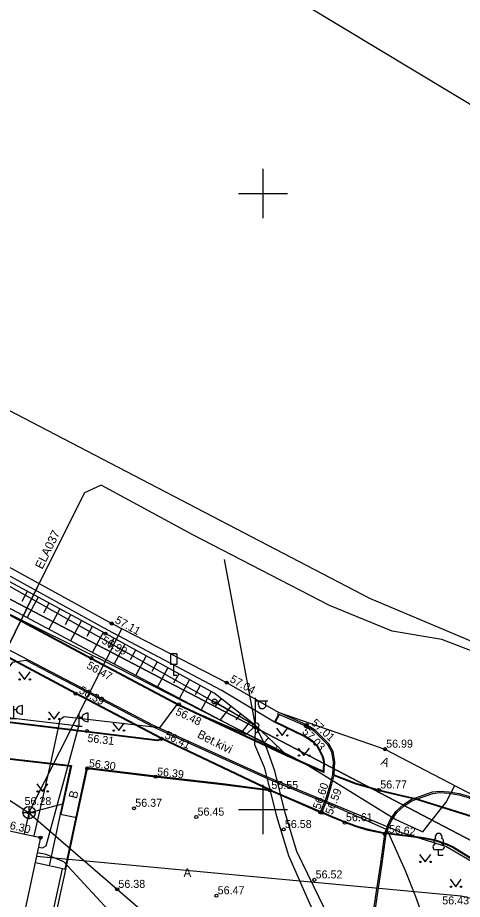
# Model space of a CAD drawing. Extents: x 542320 to 543602, y 6558748 to 6559969.
# Drawn here: x 543080.1 to 543116.2, y 6558892.7 to 6558964.3 of the extents above; entities that cross this region are included whole.
import ezdxf

# ---------------------------------------------------------------- set-up
doc = ezdxf.new("R2010")
doc.units = 0
for name, color, linetype in [('HALJASTUS', 7, 'Continuous'), ('HOONE', 7, 'Continuous'), ('HOONEDET', 7, 'Continuous'), ('KKAEV', 7, 'Continuous'), ('KORGUS-EH2000', 7, 'Continuous'), ('KTRASS', 7, 'Continuous'), ('LIIKLUS', 7, 'Continuous'), ('mootpiir', 7, 'Continuous'), ('MPKAABEL', 7, 'Continuous'), ('MPOHULIIN', 7, 'Continuous'), ('PIIR', 7, 'Continuous'), ('POST', 7, 'Continuous'), ('PUU', 7, 'Continuous'), ('RELJEEF', 7, 'Continuous'), ('SITRASS', 7, 'Continuous'), ('TEE', 7, 'Continuous'), ('VORK', 7, 'Continuous')]:
    doc.layers.add(name, color=color, linetype=linetype)

# ---------------------------------------------------------------- blocks, each defined once
blk = doc.blocks.new('VKORIS')
for p, q in [((0, 4), (0, -4)), ((-4, 0), (4, 0))]:
    blk.add_line(p, q)
blk = doc.blocks.new('LEHTP1')
for p, q in [((0.48, 0.95), (-0.48, 0.95)), ((0, 0), (0, 0.95)), ((0.76, 0), (0, 0))]:
    blk.add_line(p, q)
for centre, radius, start, end in [((0, 3.04), 0.554, 332.5799, 207.4201), ((-0.47, 1.42), 0.475, 90.0016, 269.3953), ((-0.34, 2.35), 0.465, 109.0217, 253.1415), ((0.34, 2.35), 0.465, 286.8508, 70.9859), ((0.47, 1.42), 0.475, 270.6047, 89.9984)]:
    blk.add_arc(centre, radius, start, end)
blk = doc.blocks.new('KAABVA')
for p, q in [((0, 2), (0, 0)), ((1.5, 0.69), (1.5, 2.09))]:
    blk.add_line(p, q)
for points in [[(-0.5, 0), (0.5, 0)], [(0.5, 1.39), (0, 1.39)]]:
    blk.add_lwpolyline(points)
blk.add_ellipse((1.5, 1.39), major_axis=(1, 0), ratio=0.7, start_param=1.570796, end_param=4.712389)
blk = doc.blocks.new('KAKAEV')
for p, q in [((-1, 0), (1, 0)), ((0, -1), (0, 1))]:
    blk.add_line(p, q)
blk.add_circle((0, 0), 1)
blk = doc.blocks.new('PUPOST')
blk.add_circle((0, 0), 0.5)
blk = doc.blocks.new('VAPOST')
for p, q in [((0, 0.5), (0, 4.5)), ((0, 4), (2, 4)), ((0.45, 3.36), (0.45, 4)), ((1.68, 3.36), (1.68, 4))]:
    blk.add_line(p, q)
blk.add_arc((1.07, 3.36), 0.613, 180, 0)
blk = doc.blocks.new('TUPOST')
blk.add_circle((0, 0), 0.4)
blk = doc.blocks.new('LIIKLM')
for points in [[(-0.5, 3.5), (-0.5, 1.8)], [(0.5, 3.5), (-0.5, 3.5)], [(0.5, 3.5), (0.5, 1.8)], [(0.5, 1.8), (-0.5, 1.8)], [(0, 1.8), (0, 0)], [(0.5, 0), (0, 0)]]:
    blk.add_lwpolyline(points)
blk = doc.blocks.new('MURU')
for p, q in [((-0.93, 1.21), (0, 0)), ((0, 0), (0.89, 1.21))]:
    blk.add_line(p, q)
for centre in [(-0.8, 0), (0.86, 0)]:
    blk.add_circle(centre, 0.11)
blk = doc.blocks.new('RING02')
blk.add_circle((0, 0), 0.25)

msp = doc.modelspace()

# ---------------------------------------------------------------- linework, layer by layer
at = {"layer": 'HOONE'}
msp.add_lwpolyline([(543034.683, 6558908.573), (543039.145, 6558923.204), (543048.898, 6558920.298), (543046.148, 6558911.034), (543052.456, 6558904.09), (543051.993, 6558903.334), (543059.743, 6558898.897), (543060.252, 6558899.636), (543066.159, 6558898.365), (543069.065, 6558900.487), (543081.93, 6558897.713), (543079.788, 6558887.775), (543071.384, 6558889.615), (543068.481, 6558887.445), (543058.412, 6558889.575), (543048.599, 6558888.632), (543044.558, 6558897.817)], close=True, dxfattribs=at)
at = {"layer": 'HOONEDET'}
for points in [[(543082.952, 6558890.426), (543083.981, 6558895.123), (543081.515, 6558895.656)], [(543082.694, 6558890.46), (543083.714, 6558895.181)]]:
    msp.add_lwpolyline(points, dxfattribs=at)
at = {"layer": 'KTRASS'}
for points in [[(543051.198, 6558905.487), (543058.296, 6558914.646), (543080.977, 6558899.722)], [(543080.977, 6558899.722), (543088.535, 6558914.669)], [(543080.977, 6558899.722), (543083.828, 6558900.481)], [(543080.977, 6558899.722), (543080.609, 6558898.013)], [(543080.977, 6558899.722), (543096.945, 6558885.936), (543103.523, 6558880.342)]]:
    msp.add_lwpolyline(points, dxfattribs=at)
at = {"layer": 'mootpiir'}
msp.add_lwpolyline([(543041.705, 6558842.986), (543026.57, 6558857.521), (543021.178, 6558871.989), (543014.73, 6558888.797), (543010.556, 6558896.706), (543004.564, 6558907.11), (542998.316, 6558921.614), (543000.462, 6558938.213), (543007.664, 6558949.977), (543004.131, 6558955.194), (543005.558, 6558957.946), (543018.426, 6558954.012), (543033.202, 6558945.57), (543039.476, 6558941.983), (543051.303, 6558935.01), (543063.018, 6558928.648), (543075.179, 6558921.966), (543087.717, 6558915.09), (543097.044, 6558910.296), (543101.236, 6558907.88), (543109.903, 6558904.892), (543122.322, 6558898.427)], dxfattribs=at)
at = {"layer": 'MPKAABEL'}
for points in [[(543081.761, 6558896.926), (543082.099, 6558896.873), (543082.395, 6558897.034), (543085.057, 6558906.769), (543079.727, 6558907.382), (543074.242, 6558908.071), (543068.825, 6558908.727), (543063.367, 6558909.397), (543058.921, 6558912.202), (543055.778, 6558916.692), (543052.723, 6558921.189), (543049.567, 6558925.65)], [(543099.398, 6558906.809), (543098.64, 6558906.09), (543093.01, 6558908.51), (543091.59, 6558906.63), (543083.86, 6558907.52), (543083.5, 6558907.27), (543082.75, 6558903.75), (543081.4, 6558897.86)], [(543099.403, 6558906.806), (543099.315, 6558905.267), (543100.092, 6558903.434), (543101.085, 6558899.465), (543102.078, 6558896.251), (543103.632, 6558892.692), (543104.216, 6558891.45), (543105.878, 6558886.662), (543106.439, 6558882.477), (543107.325, 6558876.083)], [(543107.994, 6558876.298), (543106.677, 6558887.105), (543105.425, 6558891.061), (543102.749, 6558896.583), (543101.807, 6558899.724), (543100.957, 6558903.142), (543100.302, 6558904.938), (543099.403, 6558906.806)], [(543091.766, 6558887.156), (543083.836, 6558895.736), (543082.377, 6558896.34), (543081.695, 6558896.464)]]:
    msp.add_lwpolyline(points, dxfattribs=at)
at = {"layer": 'MPOHULIIN'}
for points in [[(543099.403, 6558906.806), (543072.616, 6558921.947), (543045.501, 6558937.03), (543017.777, 6558952.769), (543011.701, 6558956.054)], [(543099.403, 6558906.806), (543096.865, 6558920.288)]]:
    msp.add_lwpolyline(points, dxfattribs=at)
at = {"layer": 'PIIR'}
for points in [[(543235.72, 6558917.37), (543226.24, 6558949.21), (543209.12, 6558971.55), (543183.76, 6558935.41), (543170.69, 6558898.72), (543148.25, 6558900.44), (543161.28, 6558946.47), (543121.11, 6558954.65), (543094.65, 6558970.58), (543074.02, 6558983.15), (543051.83, 6558996.48), (543031.19, 6559010.92), (543034.99, 6559017.73), (543009.89, 6559032.26), (543005.81, 6559024.69), (542993.18, 6559032.71), (542980.44, 6559040.79), (542948.42, 6559065.27)], [(543133.64, 6558888.72), (543040.58, 6558937.38), (543035.44, 6558940.39), (542997.88, 6558962.4), (542987.35, 6558968.48), (542985.46, 6558965.33), (542959.34, 6558980.79), (542961.33, 6558984.1), (542942.14, 6558992.15), (542929.74, 6558997.94), (542900.76, 6559010.27), (542901.6, 6559029.9)], [(542901.6, 6559029.9), (542917.01, 6559022.75), (542962.12, 6559001.91), (542973.99, 6558994.27), (542985.8, 6558986.59), (542988.44, 6558985.08), (543008.85, 6558971.63), (543009.57, 6558972.89), (543032.02, 6558958.19), (543053.45, 6558946.21), (543074.81, 6558934.76), (543108.64, 6558917.15), (543148.25, 6558900.44)], [(543035.44, 6558940.39), (543040.58, 6558937.38), (543133.64, 6558888.72), (543159.27, 6558882.37), (543180.35, 6558877.33), (543188.6, 6558877.87), (543138.85, 6558855), (543136.39, 6558853.9), (543124.53, 6558851.31), (543111.21, 6558848.45), (543108.75, 6558866.73), (543082.72, 6558864.15), (543047.4, 6558848.41), (543054.87, 6558832.91), (543045.52, 6558829.45), (543026.29, 6558871.02), (543014.78, 6558890.86), (543006.52, 6558905.62), (543035.44, 6558940.39)]]:
    msp.add_lwpolyline(points, dxfattribs=at)
at = {"layer": 'POST'}
msp.add_lwpolyline([(543096.06, 6558908.757), (543099.403, 6558906.806)], dxfattribs=at)
at = {"layer": 'RELJEEF'}
for points in [[(543101.897, 6558904.434), (543099.403, 6558906.806), (543096.044, 6558909.437), (543087.206, 6558914.268), (543074.649, 6558921.041), (543062.51, 6558927.7), (543050.982, 6558934.283), (543039.149, 6558941.077)], [(543037.968, 6558939.072), (543049.987, 6558932.338), (543073.674, 6558919.4), (543086.307, 6558912.668), (543095.539, 6558907.795), (543101.897, 6558904.434)], [(543080.852, 6558917.695), (543080.408, 6558916.872)], [(543081.732, 6558917.22), (543080.846, 6558915.578)], [(543082.612, 6558916.746), (543082.171, 6558915.927)], [(543083.493, 6558916.271), (543082.611, 6558914.637)], [(543084.373, 6558915.796), (543083.933, 6558914.982)], [(543085.253, 6558915.322), (543084.376, 6558913.697)], [(543086.133, 6558914.847), (543085.696, 6558914.037)], [(543087.013, 6558914.372), (543086.141, 6558912.756)], [(543087.891, 6558913.894), (543087.454, 6558913.094)], [(543088.769, 6558913.414), (543087.901, 6558911.827)], [(543089.646, 6558912.934), (543089.216, 6558912.147)], [(543090.524, 6558912.455), (543089.67, 6558910.893)], [(543091.401, 6558911.975), (543090.978, 6558911.201)], [(543092.278, 6558911.495), (543091.439, 6558909.959)], [(543093.156, 6558911.016), (543092.74, 6558910.254)], [(543094.033, 6558910.536), (543093.208, 6558909.026)], [(543094.911, 6558910.056), (543094.502, 6558909.308)], [(543095.788, 6558909.577), (543094.977, 6558908.092)], [(543096.602, 6558909), (543096.112, 6558908.375)], [(543097.389, 6558908.383), (543096.521, 6558907.276)], [(543098.176, 6558907.767), (543097.798, 6558907.284)], [(543098.964, 6558907.15), (543098.318, 6558906.326)], [(543099.723, 6558906.501), (543099.433, 6558906.196)], [(543100.448, 6558905.812), (543100.06, 6558905.405)], [(543101.172, 6558905.123), (543101.076, 6558905.021)]]:
    msp.add_lwpolyline(points, dxfattribs=at)
at = {"layer": 'SITRASS'}
for points in [[(543005.218, 6558957.454), (543044.997, 6558934.01), (543059.196, 6558926.752), (543074.381, 6558918.33), (543088.205, 6558911.502)], [(543121.901, 6558892.876), (543114.85, 6558896.99), (543111.27, 6558898.1), (543100.18, 6558902.69), (543091.12, 6558906.8), (543079.2, 6558913.04), (543070.5, 6558917.82), (543064.13, 6558921.1), (543057.19, 6558925.02), (543052.3, 6558927.95), (543046.23, 6558931.08), (543041.478, 6558932.313)], [(543150.381, 6558900.817), (543149.118, 6558899.488), (543147.687, 6558899.611), (543141.92, 6558901.373), (543128.068, 6558907.732), (543119.398, 6558911.928), (543114.519, 6558913.803), (543110.489, 6558914.465), (543105.407, 6558916.546), (543094.307, 6558922.284), (543086.864, 6558926.326), (543085.516, 6558925.687), (543081.664, 6558918.001), (543078.063, 6558910.75), (543076.812, 6558907.966), (543074.612, 6558904.543), (543073.274, 6558901.882), (543072.923, 6558901.455), (543072.094, 6558901.248), (543068.398, 6558901.619), (543067.64, 6558901.649), (543066.401, 6558900.344), (543064.442, 6558898.816)], [(543073.274, 6558901.882), (543074.612, 6558904.543), (543076.812, 6558907.966), (543078.063, 6558910.75), (543081.664, 6558918.001), (543085.516, 6558925.687)], [(543064.33, 6558898.99), (543071.83, 6558902.87), (543075.21, 6558904.44), (543076.8, 6558907.47), (543078.66, 6558910.58), (543079.69, 6558911.96), (543080.74, 6558912.11), (543085.83, 6558909.45), (543091.08, 6558906.71), (543100.42, 6558902.47), (543106.04, 6558900.15), (543110.07, 6558898.37), (543111.55, 6558895.04), (543112.38, 6558892.93), (543113.811, 6558888.962)], [(543088.205, 6558911.502), (543103.301, 6558903.795), (543110.777, 6558899.176), (543112.984, 6558898.176), (543114.876, 6558900.59), (543115.585, 6558901.933)], [(543081.607, 6558896.215), (543100.69, 6558894.43), (543116.1, 6558892.98), (543120.82, 6558891.87), (543122.17, 6558891.55), (543123.964, 6558891.034)]]:
    msp.add_lwpolyline(points, dxfattribs=at)
at = {"layer": 'TEE'}
for points in [[(543039.476, 6558941.983), (543051.303, 6558935.01), (543063.018, 6558928.648), (543075.179, 6558921.966), (543087.717, 6558915.09), (543097.044, 6558910.296), (543101.236, 6558907.88)], [(543100.939, 6558907.078), (543096.605, 6558909.676), (543087.4, 6558914.549), (543074.818, 6558921.463), (543062.815, 6558928.334), (543051.193, 6558934.777), (543039.337, 6558941.411)], [(543037.628, 6558938.816), (543049.652, 6558932.038), (543061.266, 6558925.532), (543073.39, 6558918.997), (543086.032, 6558912.226), (543093.141, 6558908.472), (543101.872, 6558904.379), (543104.96, 6558903.002), (543104.998, 6558903.893), (543104.894, 6558904.285), (543104.476, 6558905.119), (543104.056, 6558905.544), (543103.371, 6558905.967), (543101.022, 6558907.105), (543101.348, 6558907.702)], [(543037.657, 6558938.868), (543049.681, 6558932.09), (543061.295, 6558925.585), (543073.418, 6558919.05), (543086.06, 6558912.279), (543093.168, 6558908.526), (543101.897, 6558904.434), (543104.904, 6558903.093), (543104.938, 6558903.886), (543104.838, 6558904.264), (543104.427, 6558905.084), (543104.018, 6558905.497), (543103.342, 6558905.914), (543100.939, 6558907.078), (543101.295, 6558907.731)], [(543042.737, 6558925.163), (543043.156, 6558929.286), (543043.417, 6558931.913), (543045.41, 6558930.807), (543047.371, 6558929.686), (543047.085, 6558929.65), (543046.647, 6558929.461), (543046.236, 6558929.178), (543045.927, 6558928.765), (543045.764, 6558928.283), (543045.654, 6558927.323), (543046.056, 6558926.337), (543046.056, 6558926.337), (543049.803, 6558924.792), (543053.881, 6558918.848), (543057.844, 6558913.069), (543060.456, 6558909.35), (543068.387, 6558908.432), (543076.995, 6558907.406), (543085.705, 6558906.357), (543091.424, 6558905.658), (543091.756, 6558905.73)], [(543042.797, 6558925.157), (543043.216, 6558929.28), (543043.468, 6558931.816), (543045.381, 6558930.755), (543047.185, 6558929.723), (543047.069, 6558929.708), (543046.618, 6558929.514), (543046.194, 6558929.222), (543045.873, 6558928.793), (543045.705, 6558928.296), (543045.593, 6558927.315), (543045.992, 6558926.336), (543045.997, 6558926.308), (543049.765, 6558924.741), (543053.832, 6558918.814), (543057.795, 6558913.035), (543060.422, 6558909.293), (543068.38, 6558908.372), (543076.988, 6558907.346), (543085.698, 6558906.297), (543091.427, 6558905.597), (543091.769, 6558905.671)], [(543100.579, 6558901.54), (543091.756, 6558905.73), (543084.794, 6558909.393), (543071.804, 6558916.315), (543060.017, 6558922.694), (543047.371, 6558929.686)], [(543100.605, 6558901.594), (543091.783, 6558905.784), (543084.822, 6558909.446), (543071.832, 6558916.368), (543060.046, 6558922.747), (543047.4, 6558929.739)], [(543104.782, 6558899.726), (543105.237, 6558900.86), (543105.593, 6558902.037), (543105.791, 6558902.807), (543105.838, 6558903.857), (543105.704, 6558904.689), (543105.352, 6558905.311), (543104.225, 6558906.436), (543103.533, 6558906.853), (543101.236, 6558907.88)], [(543104.671, 6558899.771), (543105.124, 6558900.9), (543105.477, 6558902.069), (543105.672, 6558902.825), (543105.718, 6558903.85), (543105.589, 6558904.649), (543105.256, 6558905.238), (543104.151, 6558906.341), (543103.477, 6558906.746), (543101.187, 6558907.77)], [(543064.383, 6558898.828), (543064.824, 6558901.004), (543065.315, 6558903.6), (543065.501, 6558904.114), (543065.786, 6558904.583), (543066.12, 6558904.945), (543066.513, 6558905.224), (543066.963, 6558905.429), (543067.522, 6558905.525), (543068.025, 6558905.508), (543076.608, 6558904.469), (543084.451, 6558903.561), (543083.588, 6558899.607)], [(543064.442, 6558898.816), (543064.883, 6558900.992), (543065.373, 6558903.584), (543065.555, 6558904.088), (543065.834, 6558904.547), (543066.16, 6558904.9), (543066.543, 6558905.172), (543066.981, 6558905.371), (543067.526, 6558905.465), (543068.02, 6558905.448), (543076.601, 6558904.409), (543084.378, 6558903.509), (543083.529, 6558899.62)], [(543083.922, 6558895.136), (543084.829, 6558899.361), (543085.69, 6558903.398), (543091.281, 6558902.716), (543096.724, 6558902.09), (543100.595, 6558901.598), (543104.692, 6558899.817)], [(543083.981, 6558895.123), (543084.888, 6558899.348), (543085.737, 6558903.332), (543091.274, 6558902.656), (543096.717, 6558902.03), (543100.579, 6558901.54), (543104.668, 6558899.762)], [(543105.769, 6558902.751), (543107.513, 6558902.069), (543109.407, 6558901.527), (543111.355, 6558901.076), (543112.325, 6558900.863)], [(543105.791, 6558902.807), (543107.532, 6558902.126), (543109.422, 6558901.585), (543111.368, 6558901.135), (543112.338, 6558900.922)], [(543108.689, 6558889.82), (543109.568, 6558895.629), (543109.891, 6558898.021), (543110.141, 6558898.727), (543110.34, 6558899.159), (543110.783, 6558899.83), (543111.401, 6558900.39), (543112.037, 6558900.795), (543112.338, 6558900.922), (543113.762, 6558901.416), (543114.345, 6558901.49), (543115.119, 6558901.431), (543115.935, 6558901.296), (543116.696, 6558901.074), (543122.322, 6558898.427)], [(543108.808, 6558889.802), (543109.687, 6558895.612), (543110.008, 6558897.993), (543110.252, 6558898.682), (543110.445, 6558899.101), (543110.875, 6558899.751), (543111.474, 6558900.294), (543112.093, 6558900.688), (543112.381, 6558900.81), (543113.79, 6558901.299), (543114.348, 6558901.369), (543115.105, 6558901.312), (543115.908, 6558901.179), (543116.653, 6558900.961), (543122.271, 6558898.318)], [(543112.32, 6558900.865), (543116.999, 6558899.392), (543121.534, 6558896.423)], [(543112.338, 6558900.922), (543117.025, 6558899.447), (543121.567, 6558896.473)], [(543083.529, 6558899.62), (543082.621, 6558895.417)], [(543083.529, 6558899.62), (543084.888, 6558899.348)], [(543109.891, 6558898.021), (543108.552, 6558898.299), (543107.564, 6558898.584), (543106.638, 6558898.927), (543105.707, 6558899.305), (543104.782, 6558899.726)], [(543109.903, 6558898.08), (543108.566, 6558898.357), (543107.583, 6558898.641), (543106.66, 6558898.983), (543105.731, 6558899.36), (543104.807, 6558899.781)], [(543122.175, 6558889.852), (543122.083, 6558890.634), (543120.06, 6558893.652), (543117.589, 6558895.551), (543115.386, 6558896.917), (543114.94, 6558897.115), (543113.99, 6558897.441), (543113.033, 6558897.64), (543112.019, 6558897.78), (543110.013, 6558898.006)], [(543122.235, 6558889.859), (543122.141, 6558890.655), (543120.104, 6558893.694), (543117.623, 6558895.6), (543115.414, 6558896.97), (543114.962, 6558897.171), (543114.006, 6558897.499), (543113.043, 6558897.699), (543112.026, 6558897.84), (543110.02, 6558898.066)]]:
    msp.add_lwpolyline(points, dxfattribs=at)

# ---------------------------------------------------------------- block references
at = {"layer": 'HALJASTUS', "xscale": 0.5, "yscale": 0.5}
for p in [(543080.636, 6558910.555), (543083.036, 6558907.328), (543088.281, 6558906.393), (543101.559, 6558905.998), (543103.325, 6558904.373), (543082.089, 6558901.459), (543113.178, 6558895.734), (543115.663, 6558893.726)]:
    msp.add_blockref('MURU', p, dxfattribs=at)
at = {"layer": 'KKAEV', "xscale": 0.5, "yscale": 0.5}
msp.add_blockref('KAKAEV', (543081, 6558899.741), dxfattribs=at)
at = {"layer": 'KORGUS-EH2000', "xscale": 0.5, "yscale": 0.5}
for p in [(543087.717, 6558915.09), (543087.206, 6558914.268), (543086.06, 6558912.279), (543097.044, 6558910.296), (543084.794, 6558909.393), (543093.168, 6558908.526), (543085.705, 6558906.357), (543103.488, 6558906.752), (543103.533, 6558906.853), (543091.756, 6558905.73), (543109.903, 6558904.892), (543085.737, 6558903.332), (543091.274, 6558902.656), (543100.579, 6558901.54), (543109.422, 6558901.585), (543089.527, 6558900.097), (543081, 6558899.741), (543094.583, 6558899.378), (543104.668, 6558899.762), (543104.782, 6558899.726), (543106.638, 6558898.927), (543101.677, 6558898.374), (543109.891, 6558898.021), (543081.93, 6558897.713), (543104.174, 6558894.282), (543088.156, 6558893.513), (543096.219, 6558892.993)]:
    msp.add_blockref('RING02', p, dxfattribs=at)
at = {"layer": 'LIIKLUS', "xscale": 0.5, "yscale": 0.5}
msp.add_blockref('LIIKLM', (543092.743, 6558910.866), dxfattribs=at)
at = {"layer": 'POST', "xscale": 0.5, "yscale": 0.5}
for name, p in [('TUPOST', (543096.06, 6558908.757)), ('VAPOST', (543099.403, 6558906.806)), ('KAABVA', (543079.727, 6558907.382)), ('KAABVA', (543085.057, 6558906.769)), ('PUPOST', (543099.403, 6558906.806))]:
    msp.add_blockref(name, p, dxfattribs=at)
at = {"layer": 'PUU', "xscale": 0.5, "yscale": 0.5}
msp.add_blockref('LEHTP1', (543114.266, 6558896.252), dxfattribs=at)
at = {"layer": 'VORK', "xscale": 0.5, "yscale": 0.5}
for p in [(543100, 6558950), (543100, 6558900)]:
    msp.add_blockref('VKORIS', p, dxfattribs=at)

# ---------------------------------------------------------------- texts
at = {"layer": 'KORGUS-EH2000'}
for s, rotation, p in [('57.11', 331.04312, (543087.922, 6558915.18)), ('56.99', 331.04312, (543086.839, 6558913.533)), ('56.47', 331.04312, (543085.622, 6558911.493)), ('57.04', 331.04312, (543097.249, 6558910.386)), ('56.39', 331.04312, (543084.999, 6558909.483)), ('56.48', 334.14981, (543092.841, 6558907.726)), ('57.01', 317.30875, (543103.868, 6558906.945)), ('57.03', 314.33693, (543103.126, 6558906.26)), ('56.31', 353.21084, (543085.714, 6558905.481)), ('56.41', 334.35847, (543091.962, 6558905.819)), ('56.30', 352.84078, (543085.835, 6558903.449)), ('56.39', 353.19532, (543091.372, 6558902.773)), ('56.60', 71.44444, (543104.639, 6558899.964)), ('56.59', 69.37725, (543105.635, 6558899.517)), ('56.30', 347.02828, (543078.92, 6558898.533)), ('56.62', 353.49551, (543110.192, 6558898.109))]:
    msp.add_text(s, height=0.65, rotation=rotation, dxfattribs=at).set_placement(p)
for s, p in [('56.99', (543110.003, 6558905.009)), ('56.55', (543100.679, 6558901.657)), ('56.77', (543109.522, 6558901.702)), ('56.28', (543080.633, 6558900.355)), ('56.37', (543089.627, 6558900.214)), ('56.45', (543094.683, 6558899.495)), ('56.61', (543106.738, 6558899.044)), ('56.58', (543101.777, 6558898.491)), ('56.52', (543104.274, 6558894.399)), ('56.38', (543088.256, 6558893.63)), ('56.47', (543096.319, 6558893.11)), ('56.43', (543114.559, 6558892.29))]:
    msp.add_text(s, height=0.65, dxfattribs=at).set_placement(p)
at = {"layer": 'SITRASS'}
msp.add_text('ELA037', height=0.7, rotation=64.0224, dxfattribs=at).set_placement((543082.081, 6558919.448))
at = {"layer": 'TEE'}
for s, rotation, p in [('Bet.kivi', 333.16993, (543094.602, 6558905.866)), ('A', 337.34289, (543109.511, 6558903.652)), ('B', 75.74051, (543084.873, 6558900.827))]:
    msp.add_text(s, height=0.7, rotation=rotation, dxfattribs=at).set_placement(p)
msp.add_text('A', height=0.7, dxfattribs=at).set_placement((543093.548, 6558894.521))

doc.saveas('drawing.dxf')
